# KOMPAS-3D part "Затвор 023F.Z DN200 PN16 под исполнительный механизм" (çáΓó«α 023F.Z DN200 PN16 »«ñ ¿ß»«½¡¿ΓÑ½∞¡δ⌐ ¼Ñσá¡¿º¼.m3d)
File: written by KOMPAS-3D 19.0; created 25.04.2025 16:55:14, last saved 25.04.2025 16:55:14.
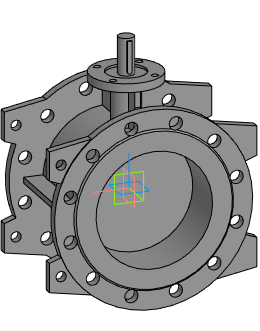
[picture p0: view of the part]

Document properties: Автор: Евгений; Полное имя файла: E:\Dendor Работа Сачек\3D для проекитирвщиков\1.7 Тип 023F.Z Затвор дисковый поворотный фланцевый с двумя эксцентриками\stp_Тип 023F.Z. Затвор под исполн. механизм\Затвор 023F.Z DN200 PN16 под исполнительный механизм.m3d

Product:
- Part/product: Затвор 023F.Z DN200 PN16 под исполнительный механизм

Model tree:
1. Операция без истории:1  (labels: Затвор 023F.Z DN200 PN16 под исполнительный механизм)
